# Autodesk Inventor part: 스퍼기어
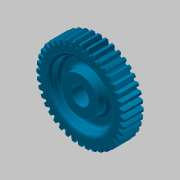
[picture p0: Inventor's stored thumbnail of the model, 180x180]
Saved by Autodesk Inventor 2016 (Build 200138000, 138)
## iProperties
Created: 2018-11
Part Number: 스퍼기어
Material: 알루미늄 6061
Document SubType Name: Modeling
Designer: mduedu
Categories: <?xml version="1.0" encoding="UTF-16"?> <MemberInstance><Categories><FamilyTemplate><FamilyTemplateParameter ValueType="xs:double" Id="1" ObjectReferenceKey="da
Density: 1 g/cm^3
Appearance: 하늘색 중간
CustomPartVersion: 1
Author: mduedu
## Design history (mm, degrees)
sketch "Sketch1"
  geometry: C1 r 42 at (0, 0)
  constraints: 1 centre point
  dimensions: "d0" = 83.99905 diameter of C1 (= da_da)
extrude "Extrusion1" new body sketch "Sketch1" distance "d1" = 19 (= da_b); taper "d2" = 0 deg
workplane "Work Plane2"
sketch "Sketch2"
  geometry: C1 r 42 at (0, 0) reference; C2 r 40.05 at (0, 0)
  constraints: 1 centre point, 1 coincident
  dimensions: "d3" = 80.10038 diameter of C2 (= da_dw)
feature "피치 지름" sketch "Sketch2" dims "d4" = 10, "d5" = 0
workplane "Work Plane8"
workplane "Work Plane9"
feature "스퍼 기어" dims "da_b" = 19, "da_d" = 80, "da_aw" = 80.10038, "da_da" = 83.99905, "da_df" = 75, "da_dw" = 80.10038, angle "da_beta" = 0 deg, "da_lefttooth" = 0, "da_righttooth" = 0
sketch "스케치3"
  geometry: L1 (-42, 19)-(42, 19) reference; L2 (42, 19)-(42, 0) reference; L3 (42, 0)-(-42, 0) reference; L4 (-42, 0)-(-42, 19) reference; L5 (0, 0)-(0, 19); L6 (42, 0)-(41, 0); L7 (42, 1)-(42, 0); L8 (42, 19)-(41, 19); L9 (42, 18)-(42, 19); L10 (41, 19)-(42, 18); L11 (41, 0)-(42, 1)
  constraints: 14 end point, 2 horizontal, 2 vertical, 1 midpoint
  dimensions: "d49" = 1 distance from line of L8.end L2; "d50" = 1 horizontal distance of L8.end L9.start; "d51" = 1 horizontal distance of L6.end L7.start; "d52" = 1 horizontal distance of L6.end L7.start
revolve "회전1" sketch "스케치3" stored, may be unused: angle "d53" = 90 deg
sketch "스케치4"
  geometry: L1 (-2.5, 8.124)-(2.5, 8.124); L2 (2.5, 8.124)-(2.5, 10.8); L3 (2.5, 10.8)-(-2.5, 10.8); L4 (-2.5, 10.8)-(-2.5, 8.124); A1 r 8.5 centre (0, 0) between (-2.5, 8.124) and (2.5, 8.124); 1 further point
  constraints: 8 end point, 2 parallel, 2 point on circle, 1 centre point, 1 coincident, 1 horizontal, 1 perpendicular
  dimensions: "d54" = 17 diameter of A1; "d56" = 19.3 dimension on A1 L3; "d57" = 5 distance of L2.end L3.end
extrude "돌출2" cut sketch "스케치4" stored distance "d58" = 10; taper "d59" = 0 deg
chamfer "모따기1" distance "d60" = 1; stored, may be unused: second distance "d61" = 2, angle "d62" = 45 deg
sketch "스케치5"
  geometry: C1 r 17.5 at (0, 0); C2 r 28.5 at (0, 0); 1 further point
  constraints: 2 centre point, 2 coincident
  dimensions: "d63" = 35 diameter of C1; "d64" = 57 diameter of C2
extrude "돌출3" cut sketch "스케치5" distance "d65" = 9.5; taper "d66" = 0 deg
fillet "모깎기1" dims "d67" = 3
body "Solid1"
body "Srf1"
node "절단 모서리 투영1"
other parameters: "d16" = 80.10038 (= da_aw), "d17" = 0, "d34" = 4.5 deg (computed from da_z), "d39" = 0, "d41" = 0, "d43" = 80.10038 (= da_aw), "d46" = 80.10038 (= da_aw), "d47" = 0, "d48" = 0
